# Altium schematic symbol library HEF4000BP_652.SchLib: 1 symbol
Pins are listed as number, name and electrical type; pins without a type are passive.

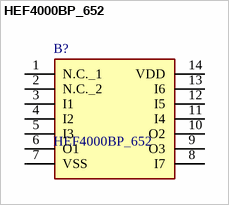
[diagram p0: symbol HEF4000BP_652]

## HEF4000BP_652
designator B?
NOR GATE; Manufacturer_Name: NXP; Manufacturer_Part_Number: HEF4000BP,652; Geometry.Height: 4.2mm
footprint DIP802W53P254L1902H420Q14N
pins: 1 N.C._1, 2 N.C._2, 3 I1, 4 I2, 5 I3, 6 O1, 7 VSS, 8 I7, 9 O3, 10 O2, 11 I4, 12 I5, 13 I6, 14 VDD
